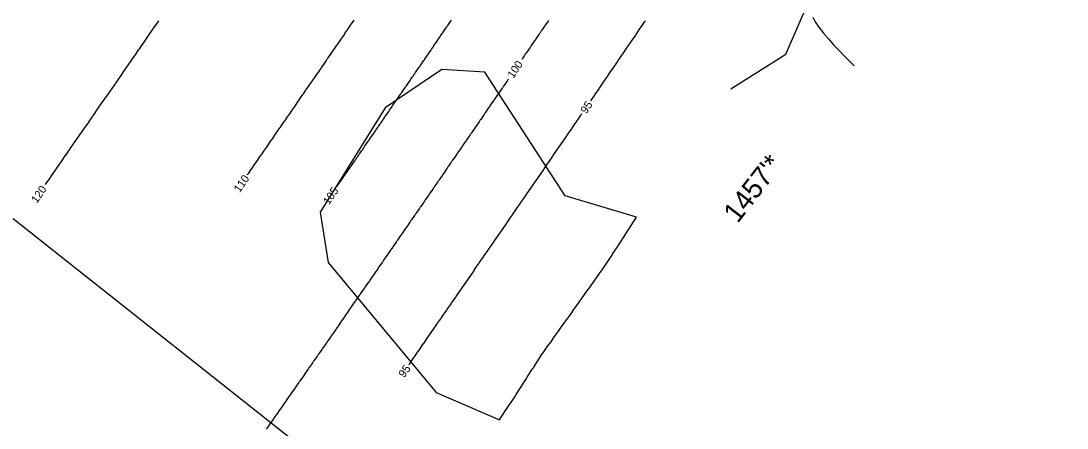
# Model space of a CAD drawing. Extents: x 1752788 to 1754108, y 472767 to 474963.
# Drawn here: x 1753208.6 to 1753338.7, y 473697 to 473747.6 of the extents above; entities that cross this region are included whole.
import ezdxf

# ---------------------------------------------------------------- set-up
doc = ezdxf.new("R2010")
doc.units = 0
for name, color, linetype in [('D_Roadway_Centerline', 7, 'Continuous'), ('D_Slope_ClearingLimitLine', 7, 'Continuous'), ('D_Slope_Toe', 7, 'Continuous'), ('M_Drainage_Ditch_Line', 7, 'Continuous'), ('P_ROW_Tie_Lines', 7, 'Continuous'), ('PARCEL DISTS', 7, 'Continuous'), ('S_Contours_Major', 7, 'Continuous')]:
    doc.layers.add(name, color=color, linetype=linetype)

msp = doc.modelspace()

# ---------------------------------------------------------------- linework, layer by layer
at = {"layer": 'D_Roadway_Centerline'}
msp.add_arc((1748084.97, 477769.75), 6500, 316.341944, 334.416944, dxfattribs=at)
at = {"layer": 'D_Slope_ClearingLimitLine'}
for p, q in [((1753303.72, 473743.48), (1753309.44, 473756.7)), ((1753296.88, 473739.2), (1753303.72, 473743.48))]:
    msp.add_line(p, q, dxfattribs=at)
msp.add_lwpolyline([(1753285.13, 473723.25), (1753276.26, 473725.88), (1753266.26, 473741.28), (1753260.92, 473741.61), (1753253.86, 473736.84), (1753245.8, 473723.87), (1753246.78, 473717.6), (1753260.21, 473701.46), (1753268.07, 473698.05), (1753268.84, 473699.21), (1753268.85, 473699.22), (1753269.41, 473700.07), (1753269.5, 473700.19), (1753269.98, 473700.91), (1753270.18, 473701.21), (1753270.63, 473701.9), (1753270.91, 473702.35), (1753271.21, 473702.81), (1753271.45, 473703.21), (1753271.54, 473703.34), (1753271.75, 473703.67), (1753272.17, 473704.34), (1753272.3, 473704.53), (1753272.8, 473705.33), (1753272.84, 473705.38), (1753273.24, 473706.01), (1753273.67, 473706.62), (1753273.81, 473706.82), (1753274.26, 473707.44), (1753274.5, 473707.77), (1753274.85, 473708.27), (1753275.18, 473708.73), (1753275.44, 473709.09), (1753275.86, 473709.68), (1753276.03, 473709.92), (1753276.54, 473710.64), (1753276.62, 473710.74), (1753277.21, 473711.57), (1753277.22, 473711.59), (1753277.79, 473712.39), (1753277.9, 473712.54), (1753278.38, 473713.22), (1753278.59, 473713.5), (1753278.97, 473714.04), (1753279.27, 473714.45), (1753279.56, 473714.86), (1753279.95, 473715.41), (1753280.15, 473715.69), (1753280.5, 473716.19), (1753280.63, 473716.36), (1753280.8, 473716.59), (1753281.49, 473717.6), (1753281.58, 473717.74), (1753282.13, 473718.6), (1753282.2, 473718.71), (1753282.68, 473719.45), (1753282.84, 473719.69), (1753285.13, 473723.25)], dxfattribs=at)
at = {"layer": 'D_Slope_Toe'}
msp.add_line((1753296.88, 473739.2), (1753303.72, 473743.48), dxfattribs=at)
at = {"layer": 'M_Drainage_Ditch_Line'}
msp.add_lwpolyline([(1753307.05, 473748.1), (1753307.37, 473747.5), (1753307.83, 473746.84), (1753308.38, 473746.12), (1753309, 473745.39), (1753309.65, 473744.67), (1753310.3, 473743.99), (1753310.9, 473743.37), (1753311.43, 473742.84), (1753311.85, 473742.43), (1753312.23, 473742.07)], dxfattribs=at)
at = {"layer": 'P_ROW_Tie_Lines'}
msp.add_line((1753185.49, 473740.51), (1753263.94, 473678.54), dxfattribs=at)
at = {"layer": 'S_Contours_Major'}
for points in [[(1753211.6, 473727.3), (1753211.86, 473727.68), (1753212.05, 473727.94), (1753212.44, 473728.5), (1753212.45, 473728.52), (1753213.01, 473729.33), (1753213.02, 473729.34), (1753213.59, 473730.16), (1753213.6, 473730.17), (1753214.16, 473730.98), (1753214.17, 473730.99), (1753214.74, 473731.81), (1753214.74, 473731.82), (1753215.31, 473732.63), (1753215.32, 473732.64), (1753215.88, 473733.46), (1753215.89, 473733.47), (1753216.46, 473734.29), (1753216.46, 473734.29), (1753217.03, 473735.11), (1753217.03, 473735.12), (1753217.61, 473735.94), (1753218.18, 473736.77), (1753218.75, 473737.6), (1753219.32, 473738.42), (1753219.9, 473739.25), (1753220.47, 473740.07), (1753221.01, 473740.85), (1753221.1, 473740.99), (1753221.31, 473741.29), (1753221.57, 473741.67), (1753221.69, 473741.84), (1753222.19, 473742.56), (1753222.74, 473743.35), (1753222.79, 473743.43), (1753223.2, 473744.02), (1753223.33, 473744.21), (1753223.46, 473744.4), (1753223.87, 473744.99), (1753223.96, 473745.11), (1753224.35, 473745.68), (1753224.47, 473745.86), (1753224.6, 473746.05), (1753225, 473746.63), (1753225.06, 473746.71), (1753225.57, 473747.45), (1753225.7, 473747.64)], [(1753236.75, 473728.52), (1753236.76, 473728.54), (1753236.89, 473728.72), (1753237.04, 473728.93), (1753237.16, 473729.11), (1753237.19, 473729.15), (1753237.33, 473729.35), (1753237.4, 473729.46), (1753237.54, 473729.66), (1753237.62, 473729.78), (1753237.9, 473730.18), (1753237.98, 473730.29), (1753238.12, 473730.49), (1753238.2, 473730.61), (1753238.47, 473731.01), (1753238.55, 473731.12), (1753238.69, 473731.32), (1753238.77, 473731.44), (1753239.05, 473731.84), (1753239.13, 473731.95), (1753239.26, 473732.15), (1753239.34, 473732.27), (1753239.62, 473732.67), (1753239.7, 473732.78), (1753239.84, 473732.98), (1753239.92, 473733.1), (1753240.19, 473733.5), (1753240.28, 473733.61), (1753240.41, 473733.81), (1753240.49, 473733.92), (1753240.77, 473734.33), (1753240.85, 473734.44), (1753240.98, 473734.64), (1753241.06, 473734.75), (1753241.34, 473735.16), (1753241.42, 473735.27), (1753241.56, 473735.47), (1753241.64, 473735.58), (1753241.92, 473735.99), (1753242, 473736.1), (1753242.13, 473736.3), (1753242.21, 473736.41), (1753242.49, 473736.82), (1753242.57, 473736.93), (1753242.7, 473737.13), (1753242.78, 473737.24), (1753243.06, 473737.65), (1753243.14, 473737.76), (1753243.27, 473737.96), (1753243.35, 473738.07), (1753243.63, 473738.48), (1753243.71, 473738.59), (1753243.85, 473738.79), (1753243.93, 473738.9), (1753244.21, 473739.31), (1753244.29, 473739.42), (1753244.42, 473739.62), (1753244.5, 473739.73), (1753244.78, 473740.14), (1753244.86, 473740.26), (1753244.99, 473740.45), (1753245.07, 473740.56), (1753245.35, 473740.97), (1753245.43, 473741.09), (1753245.56, 473741.28), (1753245.64, 473741.39), (1753245.94, 473741.82), (1753245.98, 473741.89), (1753246.08, 473742.02), (1753246.11, 473742.07), (1753246.3, 473742.34), (1753246.39, 473742.48), (1753246.52, 473742.67), (1753246.56, 473742.72), (1753246.71, 473742.94), (1753246.79, 473743.05), (1753247.07, 473743.46), (1753247.15, 473743.58), (1753247.28, 473743.77), (1753247.36, 473743.88), (1753247.64, 473744.3), (1753247.72, 473744.41), (1753247.85, 473744.6), (1753247.93, 473744.71), (1753248.21, 473745.13), (1753248.29, 473745.24), (1753248.42, 473745.43), (1753248.5, 473745.54), (1753248.79, 473745.96), (1753248.86, 473746.07), (1753248.99, 473746.26), (1753249.07, 473746.37), (1753249.36, 473746.79), (1753249.44, 473746.9), (1753249.57, 473747.09), (1753249.64, 473747.21), (1753249.93, 473747.62), (1753250.01, 473747.73)], [(1753247.91, 473727.11), (1753248.06, 473727.33), (1753248.16, 473727.46), (1753248.36, 473727.75), (1753248.42, 473727.84), (1753248.48, 473727.93), (1753248.64, 473728.16), (1753248.73, 473728.29), (1753248.93, 473728.58), (1753248.99, 473728.67), (1753249.06, 473728.76), (1753249.21, 473728.99), (1753249.31, 473729.12), (1753249.51, 473729.41), (1753249.57, 473729.5), (1753249.63, 473729.59), (1753249.79, 473729.82), (1753249.88, 473729.96), (1753250.08, 473730.24), (1753250.14, 473730.33), (1753250.21, 473730.42), (1753250.36, 473730.65), (1753250.46, 473730.79), (1753250.65, 473731.07), (1753250.72, 473731.17), (1753250.78, 473731.26), (1753250.94, 473731.48), (1753251.03, 473731.62), (1753251.23, 473731.91), (1753251.29, 473732), (1753251.35, 473732.09), (1753251.51, 473732.31), (1753251.6, 473732.45), (1753251.8, 473732.74), (1753251.86, 473732.83), (1753251.93, 473732.92), (1753252.08, 473733.15), (1753252.18, 473733.28), (1753252.37, 473733.57), (1753252.44, 473733.66), (1753252.5, 473733.75), (1753252.66, 473733.98), (1753252.75, 473734.12), (1753252.95, 473734.4), (1753253.01, 473734.49), (1753253.07, 473734.58), (1753253.23, 473734.81), (1753253.32, 473734.95), (1753253.52, 473735.23), (1753253.58, 473735.32), (1753253.65, 473735.41), (1753253.81, 473735.65), (1753253.88, 473735.76), (1753254.01, 473735.94), (1753254.07, 473736.02), (1753254.18, 473736.19), (1753254.31, 473736.37), (1753254.42, 473736.54), (1753254.67, 473736.89), (1753254.73, 473736.99), (1753254.79, 473737.08), (1753254.95, 473737.31), (1753255.04, 473737.44), (1753255.24, 473737.73), (1753255.3, 473737.82), (1753255.37, 473737.91), (1753255.52, 473738.14), (1753255.62, 473738.28), (1753255.81, 473738.56), (1753255.87, 473738.65), (1753255.94, 473738.74), (1753256.1, 473738.97), (1753256.19, 473739.11), (1753256.38, 473739.39), (1753256.45, 473739.48), (1753256.51, 473739.57), (1753256.67, 473739.8), (1753256.76, 473739.94), (1753256.96, 473740.22), (1753257.02, 473740.31), (1753257.08, 473740.41), (1753257.24, 473740.64), (1753257.34, 473740.77), (1753257.53, 473741.05), (1753257.59, 473741.15), (1753257.66, 473741.24), (1753257.81, 473741.47), (1753257.91, 473741.61), (1753258.1, 473741.89), (1753258.16, 473741.98), (1753258.23, 473742.07), (1753258.39, 473742.3), (1753258.48, 473742.44), (1753258.67, 473742.72), (1753258.74, 473742.81), (1753258.8, 473742.9), (1753258.96, 473743.13), (1753259.05, 473743.27), (1753259.24, 473743.55), (1753259.31, 473743.64), (1753259.37, 473743.74), (1753259.53, 473743.97), (1753259.63, 473744.11), (1753259.82, 473744.38), (1753259.88, 473744.48), (1753259.94, 473744.57), (1753260.1, 473744.8), (1753260.2, 473744.94), (1753260.39, 473745.21), (1753260.45, 473745.31), (1753260.51, 473745.4), (1753260.67, 473745.63), (1753260.77, 473745.77), (1753260.96, 473746.05), (1753261.02, 473746.14), (1753261.09, 473746.23), (1753261.25, 473746.47), (1753261.34, 473746.61), (1753261.53, 473746.88), (1753261.59, 473746.97), (1753261.66, 473747.07), (1753261.82, 473747.3), (1753261.91, 473747.44), (1753262.1, 473747.71)], [(1753274.17, 473747.67), (1753274.14, 473747.62), (1753273.8, 473747.13), (1753273.7, 473746.98), (1753273.36, 473746.49), (1753273.29, 473746.38), (1753273.14, 473746.17), (1753273.03, 473746.01), (1753272.99, 473745.95), (1753272.62, 473745.41), (1753272.57, 473745.33), (1753272.46, 473745.17), (1753272.42, 473745.12), (1753272.05, 473744.58), (1753272, 473744.5), (1753271.89, 473744.33), (1753271.85, 473744.28), (1753271.46, 473743.71), (1753271.42, 473743.65), (1753271.3, 473743.48), (1753271.21, 473743.34), (1753271.18, 473743.3), (1753270.91, 473742.91), (1753270.88, 473742.86)], [(1753279.45, 473737.71), (1753279.89, 473738.36), (1753279.94, 473738.43), (1753280.47, 473739.2), (1753280.52, 473739.27), (1753281.04, 473740.03), (1753281.12, 473740.15), (1753281.52, 473740.73), (1753281.65, 473740.93), (1753281.79, 473741.12), (1753282.19, 473741.71), (1753282.23, 473741.78), (1753282.76, 473742.54), (1753282.81, 473742.61), (1753283.33, 473743.38), (1753283.38, 473743.45), (1753283.9, 473744.21), (1753283.95, 473744.29), (1753284.47, 473745.05), (1753284.52, 473745.12), (1753285.04, 473745.88), (1753285.09, 473745.96), (1753285.61, 473746.72), (1753285.66, 473746.8), (1753286.18, 473747.56), (1753286.24, 473747.63)], [(1753269.19, 473740.39), (1753269.14, 473740.32), (1753269.03, 473740.16), (1753268.99, 473740.11), (1753268.62, 473739.57), (1753268.56, 473739.49), (1753268.46, 473739.33), (1753268.42, 473739.28), (1753268.05, 473738.73), (1753267.99, 473738.65), (1753267.88, 473738.5), (1753267.85, 473738.45), (1753267.47, 473737.9), (1753267.42, 473737.82), (1753267.31, 473737.66), (1753267.28, 473737.61), (1753266.9, 473737.06), (1753266.85, 473736.99), (1753266.74, 473736.83), (1753266.7, 473736.78), (1753266.33, 473736.23), (1753266.27, 473736.15), (1753266.17, 473736), (1753266.13, 473735.95), (1753265.75, 473735.4), (1753265.7, 473735.32), (1753265.59, 473735.16), (1753265.56, 473735.11), (1753265.18, 473734.56), (1753265.13, 473734.49), (1753265.02, 473734.33), (1753264.98, 473734.28), (1753264.61, 473733.73), (1753264.55, 473733.65), (1753264.45, 473733.5), (1753264.41, 473733.44), (1753264.03, 473732.9), (1753263.98, 473732.82), (1753263.87, 473732.66), (1753263.84, 473732.61), (1753263.46, 473732.06), (1753263.41, 473731.98), (1753263.3, 473731.83), (1753263.26, 473731.78), (1753262.88, 473731.23), (1753262.83, 473731.15), (1753262.72, 473730.99), (1753262.69, 473730.94), (1753262.3, 473730.38), (1753262.22, 473730.27), (1753262.06, 473730.04), (1753261.97, 473729.9), (1753261.74, 473729.56), (1753261.68, 473729.48), (1753261.58, 473729.33), (1753261.54, 473729.28), (1753261.16, 473728.73), (1753261.11, 473728.65), (1753261, 473728.5), (1753260.97, 473728.44), (1753260.59, 473727.89), (1753260.53, 473727.82), (1753260.43, 473727.66), (1753260.39, 473727.61), (1753260.01, 473727.06), (1753259.96, 473726.98), (1753259.85, 473726.83), (1753259.82, 473726.78), (1753259.44, 473726.23), (1753259.39, 473726.15), (1753259.28, 473726), (1753259.24, 473725.95), (1753258.86, 473725.4), (1753258.81, 473725.32), (1753258.7, 473725.16), (1753258.67, 473725.11), (1753258.29, 473724.56), (1753258.24, 473724.49), (1753258.13, 473724.33), (1753258.09, 473724.28), (1753257.71, 473723.73), (1753257.66, 473723.65), (1753257.55, 473723.5), (1753257.52, 473723.45), (1753257.14, 473722.9), (1753257.08, 473722.82), (1753256.98, 473722.67), (1753256.94, 473722.62), (1753256.56, 473722.06), (1753256.51, 473721.99), (1753256.4, 473721.84), (1753256.37, 473721.78), (1753255.99, 473721.23), (1753255.93, 473721.16), (1753255.83, 473721), (1753255.79, 473720.95), (1753255.41, 473720.4), (1753255.36, 473720.32), (1753255.25, 473720.17), (1753255.22, 473720.12), (1753254.84, 473719.57), (1753254.78, 473719.49), (1753254.68, 473719.34), (1753254.64, 473719.29), (1753254.26, 473718.73), (1753254.21, 473718.66), (1753254.1, 473718.51), (1753254.07, 473718.46), (1753253.68, 473717.9), (1753253.63, 473717.83), (1753253.53, 473717.67), (1753253.49, 473717.62), (1753253.1, 473717.06), (1753252.99, 473716.91), (1753252.78, 473716.59), (1753252.7, 473716.48), (1753252.53, 473716.24), (1753252.48, 473716.16), (1753252.37, 473716.01), (1753252.34, 473715.96), (1753251.95, 473715.41), (1753251.9, 473715.33), (1753251.8, 473715.18), (1753251.76, 473715.13), (1753251.38, 473714.57), (1753251.32, 473714.5), (1753251.22, 473714.35), (1753251.18, 473714.29), (1753250.8, 473713.74), (1753250.75, 473713.67), (1753250.64, 473713.51), (1753250.61, 473713.46), (1753250.22, 473712.91), (1753250.17, 473712.83), (1753250.07, 473712.68), (1753250.03, 473712.63), (1753249.65, 473712.08), (1753249.59, 473712), (1753249.49, 473711.85), (1753249.45, 473711.8), (1753249.07, 473711.25), (1753249.02, 473711.17), (1753248.91, 473711.02), (1753248.88, 473710.97), (1753248.49, 473710.42), (1753248.44, 473710.34), (1753248.33, 473710.19), (1753248.3, 473710.14), (1753247.92, 473709.58), (1753247.86, 473709.51), (1753247.76, 473709.36), (1753247.72, 473709.3), (1753247.34, 473708.75), (1753247.28, 473708.68), (1753247.18, 473708.52), (1753247.14, 473708.47), (1753246.76, 473707.92), (1753246.71, 473707.85), (1753246.6, 473707.69), (1753246.57, 473707.64), (1753246.18, 473707.09), (1753246.13, 473707.01), (1753246.02, 473706.86), (1753245.99, 473706.81), (1753245.6, 473706.26), (1753245.55, 473706.18), (1753245.45, 473706.03), (1753245.41, 473705.98), (1753245.03, 473705.43), (1753244.97, 473705.35), (1753244.87, 473705.2), (1753244.83, 473705.15), (1753244.45, 473704.6), (1753244.39, 473704.52), (1753244.29, 473704.37), (1753244.25, 473704.32), (1753243.86, 473703.76), (1753243.74, 473703.58), (1753243.45, 473703.17), (1753243.4, 473703.09), (1753243.27, 473702.91), (1753243.15, 473702.73), (1753243.1, 473702.65), (1753242.71, 473702.11), (1753242.66, 473702.03), (1753242.55, 473701.88), (1753242.52, 473701.82), (1753242.13, 473701.27), (1753242.08, 473701.2), (1753241.97, 473701.04), (1753241.94, 473700.99), (1753241.56, 473700.44), (1753241.5, 473700.37), (1753241.39, 473700.21), (1753241.36, 473700.16), (1753240.98, 473699.61), (1753240.92, 473699.54), (1753240.82, 473699.38), (1753240.78, 473699.33), (1753240.4, 473698.78), (1753240.34, 473698.71), (1753240.24, 473698.55), (1753240.2, 473698.5), (1753239.82, 473697.95), (1753239.76, 473697.88), (1753239.66, 473697.72), (1753239.62, 473697.67), (1753239.24, 473697.12), (1753239.18, 473697.05), (1753239.08, 473696.89)], [(1753256.83, 473704.92), (1753256.88, 473704.99), (1753256.92, 473705.05), (1753257.45, 473705.82), (1753257.5, 473705.89), (1753258.03, 473706.65), (1753258.08, 473706.72), (1753258.61, 473707.49), (1753258.66, 473707.55), (1753259.19, 473708.32), (1753259.23, 473708.39), (1753259.77, 473709.15), (1753259.81, 473709.22), (1753260.34, 473709.99), (1753260.39, 473710.05), (1753260.63, 473710.4), (1753260.65, 473710.43), (1753260.95, 473710.85), (1753260.96, 473710.88), (1753261.5, 473711.66), (1753261.54, 473711.72), (1753262.08, 473712.49), (1753262.12, 473712.55), (1753262.65, 473713.32), (1753262.7, 473713.39), (1753263.23, 473714.16), (1753263.27, 473714.22), (1753263.81, 473714.99), (1753263.85, 473715.05), (1753264.38, 473715.82), (1753264.43, 473715.89), (1753264.96, 473716.66), (1753265, 473716.72), (1753265.54, 473717.49), (1753265.58, 473717.55), (1753266.11, 473718.32), (1753266.16, 473718.39), (1753266.69, 473719.16), (1753266.73, 473719.22), (1753267.26, 473719.99), (1753267.31, 473720.06), (1753267.84, 473720.83), (1753267.88, 473720.89), (1753268.41, 473721.66), (1753268.46, 473721.73), (1753268.99, 473722.49), (1753269.03, 473722.56), (1753269.56, 473723.33), (1753269.61, 473723.39), (1753269.93, 473723.86), (1753269.95, 473723.89), (1753270.17, 473724.2), (1753270.18, 473724.22), (1753270.71, 473725), (1753270.76, 473725.06), (1753271.29, 473725.83), (1753271.34, 473725.9), (1753271.87, 473726.67), (1753271.91, 473726.73), (1753272.44, 473727.5), (1753272.48, 473727.57), (1753273.01, 473728.34), (1753273.06, 473728.4), (1753273.59, 473729.18), (1753273.63, 473729.24), (1753274.16, 473730.01), (1753274.21, 473730.07), (1753274.74, 473730.84), (1753274.78, 473730.91), (1753275.31, 473731.68), (1753275.36, 473731.74), (1753275.88, 473732.51), (1753275.93, 473732.58), (1753276.46, 473733.35), (1753276.5, 473733.42), (1753277.03, 473734.18), (1753277.08, 473734.25), (1753277.6, 473735.02), (1753277.65, 473735.09), (1753278.18, 473735.85), (1753278.22, 473735.92), (1753278.33, 473736.07)]]:
    msp.add_lwpolyline(points, dxfattribs=at)

# ---------------------------------------------------------------- texts
at = {"layer": 'PARCEL DISTS'}
msp.add_text("1457'*", height=2.49, rotation=52.2581, dxfattribs=at).set_placement((1753297.72, 473722.39))
at = {"layer": 'S_Contours_Major'}
for s, rotation, p in [('100', 55.5565, (1753269.8, 473740.42)), ('95', 55.5663, (1753278.89, 473736.01)), ('110', 55.2838, (1753235.77, 473726.23)), ('120', 55.149, (1753210.54, 473724.9)), ('105', 55.329, (1753246.86, 473724.7)), ('95', 55.2187, (1753256.25, 473703.22))]:
    msp.add_text(s, height=0.996, rotation=rotation, dxfattribs=at).set_placement(p)

doc.saveas('drawing.dxf')
